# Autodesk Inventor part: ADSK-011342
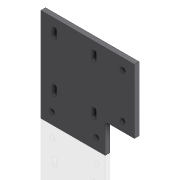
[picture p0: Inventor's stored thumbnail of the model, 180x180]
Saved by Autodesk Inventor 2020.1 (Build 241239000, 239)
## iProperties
Created: 1999-12
Part Number: ADSK-011342
Material: Acier doux
Description: PLT-44,FH,CP,03,080,080,MNT,SERVO
Document SubType Name: Modeling
Designer: sspink
Density: 7.86 g/cm^3
Appearance: Metal-Steel(Polish)
Mass: 2841.11 g
Surface Area: 838.133 cm^2
Volume: 361.464 cm^3
Control State: 0
Checked Out: False
Master: False
Shininess: 0.0
Length Units: 11269
Angle Units: 11279
Time Units: 11290
Mass Units: 11283
Length Display Precision: 3
Angle Display Precision: 2
Compacted: True
Dimensions: 203x203x10 mm
Mass: 2,841 kg
DocNumber: ADSK-011342.ipt
Folder: 01 - Themengebiete\Simplification\01 - Packaging machine\
VDS_Category: 3D Komponenten
Density: 0.0
Volumn: 0.0
Area: 0.0
PropertySet Name: Model Information
Author: sspink
Revision Number: -
Title: base plate
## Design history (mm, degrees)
workpoint "Arbeitspunkt7"
workpoint "Arbeitspunkt8"
workaxis "Arbeitsachse7"
  workpoint "Arbeitspunkt5"
workaxis "Arbeitsachse8"
  workpoint "Arbeitspunkt6"
workaxis "Arbeitsachse9"
workaxis "Arbeitsachse10"
node "Solide1"
  node "Extrusion1" dims "d2" = 10, "d3" = 0
  node "Hole1" dims "d10" = 10.31875, "d11" = 9.525, "d12" = 6.35, "d13" = 60 deg, "d14" = 19.05, "d15" = 118 deg
  node "Extrusion2" dims "d26" = 9.525, "d27" = 0
  node "Extrusion3" dims "d37" = 25.4, "d38" = 0
  node "Fillet1" dims "d39" = 6.35
sketch "Sketch1"
  geometry: L1 (101.5, -101.5)-(-101.5, -101.5); L2 (-101.5, -101.5)-(-101.5, 101.5); L3 (-101.5, 101.5)-(101.5, 101.5); L4 (101.5, 101.5)-(101.5, -101.5); 3 further points
  constraints: 8 end point, 2 midpoint, 2 parallel, 1 horizontal, 1 horizontal alignment, 1 perpendicular, 1 vertical alignment
  dimensions: "d0" = 203 distance of L1.start L1.end (= d1); "d1" = 203 distance of L1.end L2.end
sketch "Sketch2"
  geometry: L1 (101.5, -101.5)-(101.5, 101.5) reference; L2 (101.5, 101.5)-(-101.5, 101.5) reference; L3 (-101.5, 101.5)-(-101.5, -101.5) reference; L4 (-101.5, -101.5)-(101.5, -101.5) reference; 4 further points
  constraints: 1 horizontal alignment, 1 vertical alignment
  dimensions: "d4" = 25 distance from line of point (-76.5, -76.5) L3; "d5" = 25 distance from line of point (-76.5, -76.5) L4 (= d4); "d8" = 23 distance from line of point (76.5, 78.5) L2; "d40" = 25 distance from line of L1 point (76.5, 78.5); "d41" = 96 distance of point (76.5, -17.5) point (76.5, 78.5); "d42" = 96 distance of point (19.5, -76.5) point (-76.5, -76.5)
sketch "Sketch4"
  geometry: L1 (-101.5, 101.5)-(101.5, 101.5) reference; L2 (-14.5, 80.25)-(-14.5, 67.75); L3 (-19, 80.25)-(-19, 67.75); L4 (-10, 67.75)-(-10, 80.25); L5 (-19.5, -76.5)-(76.5, -76.5); L6 (71.5, 80.25)-(71.5, 67.75); L7 (76, 67.75)-(76, 80.25); L8 (67, 80.25)-(67, 67.75); L9 (-14.5, 74)-(71.5, 74); L10 (71.5, 74)-(71.5, -34); L11 (71.5, -34)-(-14.5, -34); L12 (-14.5, -34)-(-14.5, 74); L13 (-19, -27.75)-(-19, -40.25); L14 (-14.5, -27.75)-(-14.5, -40.25); L15 (-10, -40.25)-(-10, -27.75); L16 (67, -27.75)-(67, -40.25); L17 (71.5, -27.75)-(71.5, -40.25); L18 (76, -40.25)-(76, -27.75); C1 r 5.159 at (-19.5, -76.5) reference; C2 r 5.159 at (76.5, -76.5) reference; A1 r 4.5 centre (-14.5, 80.25) between (-10, 80.25) and (-19, 80.25); A2 r 4.5 centre (-14.5, 67.75) between (-19, 67.75) and (-10, 67.75); A3 r 4.5 centre (71.5, 80.25) between (76, 80.25) and (67, 80.25); A4 r 4.5 centre (71.5, 67.75) between (67, 67.75) and (76, 67.75); A5 r 4.5 centre (-14.5, -27.75) between (-10, -27.75) and (-19, -27.75); A6 r 4.5 centre (-14.5, -40.25) between (-19, -40.25) and (-10, -40.25); A7 r 4.5 centre (71.5, -27.75) between (76, -27.75) and (67, -27.75); A8 r 4.5 centre (71.5, -40.25) between (67, -40.25) and (76, -40.25); 7 further points
  constraints: 42 end point, 16 point on circle, 16 tangent, 8 centre point, 6 midpoint, 6 parallel, 5 coincident, 4 vertical, 2 horizontal, 1 perpendicular, 1 vertical alignment
  dimensions: "d46" = 12.5 distance of L2.start L2.end; "d47" = 4.5 radius of A2; "d48" = 12.5 distance of L6.start L6.end; "d49" = 4.5 radius of A4; "d50" = 108 distance of L11.end L9.start; "d51" = 86 distance of L9.start L9.end; "d52" = 12.5 distance of L14.start L14.end; "d53" = 4.5 radius of A6; "d54" = 12.5 distance of L17.start L17.end; "d55" = 4.5 radius of A8; "d56" = 27.5 distance between parallel lines of L1 L9
node "Corps solides"
node "Corps surfaciques"
sketch "Sketch5"
  geometry: L1 (-101.5, -101.5)-(-101.5, 101.5) reference; L2 (101.5, -101.5)-(-101.5, -101.5) reference; L3 (101.5, 101.5)-(101.5, -101.5) reference; L4 (-101.5, -38)-(-38, -38); L5 (-38, -38)-(-38, -101.5)
  constraints: 4 end point, 2 perpendicular, 2 point on line
  dimensions: "d35" = 63.5 distance between parallel lines of L5 L1; "d36" = 63.5 distance between parallel lines of L4 L2
